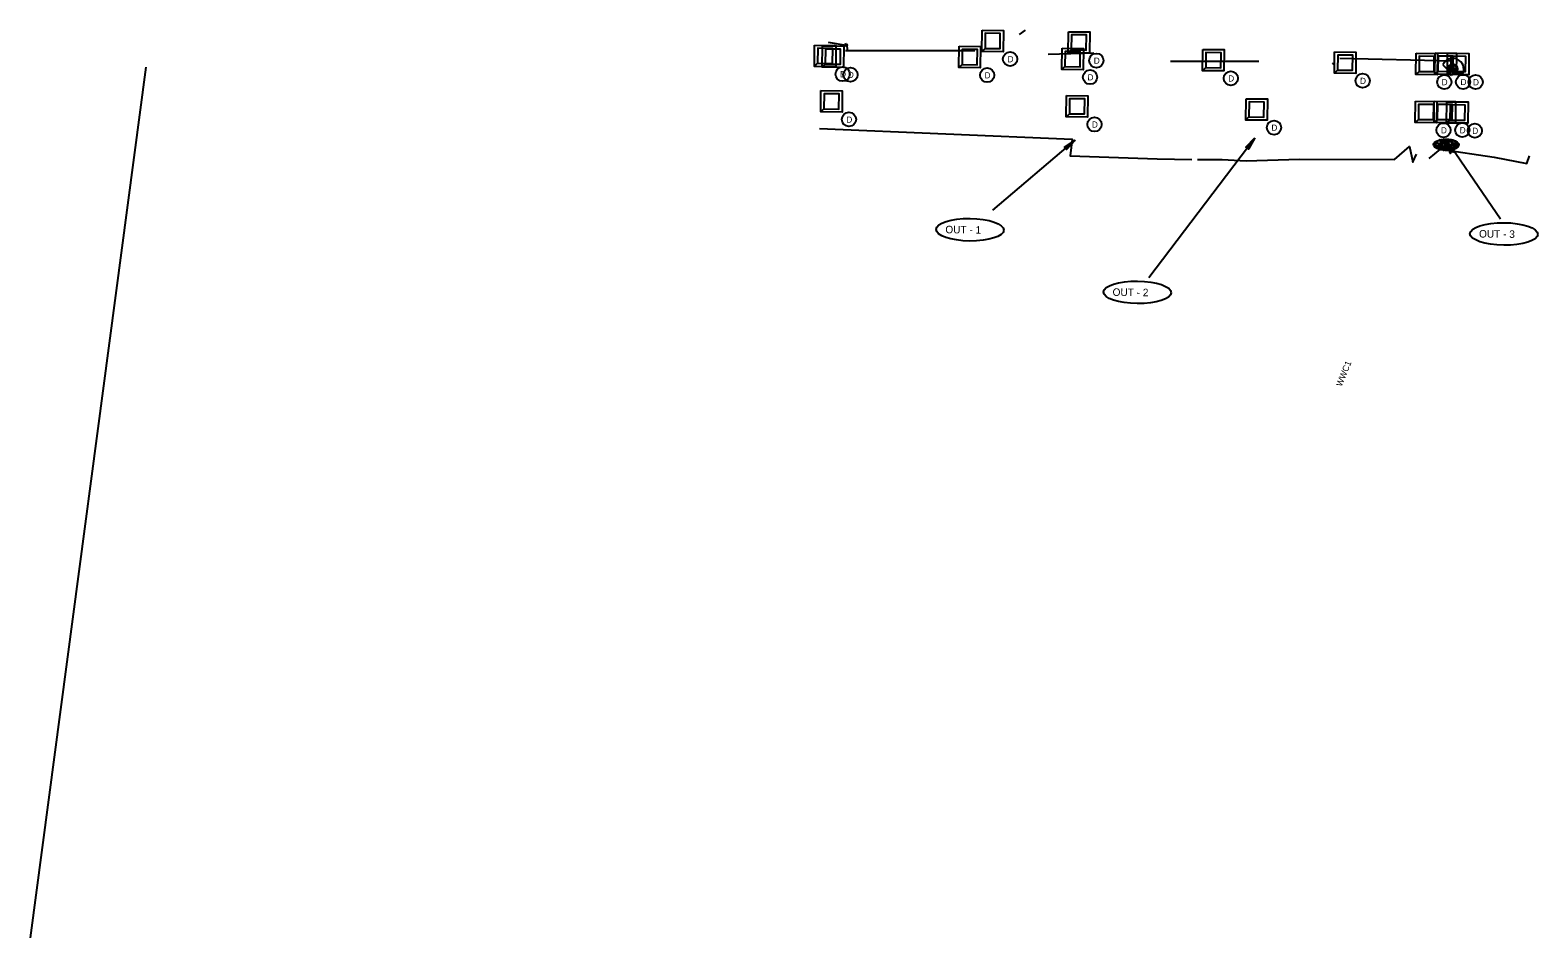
# Model space of a CAD drawing. Extents: x 1200000 to 1692190, y 507547 to 1200000.
# Drawn here: x 1680830 to 1682031, y 517488 to 518211 of the extents above; entities that cross this region are included whole.
import ezdxf

# ---------------------------------------------------------------- set-up
doc = ezdxf.new("R2010")
doc.units = 0
for name, color, linetype in [('DESIGN - EROSION CONTROL - Devices', 7, 'Continuous'), ('DESIGN - EROSION CONTROL - Devices Text and Legends', 7, 'Continuous'), ('SURVEY - MISCELLANEOUS - Office with Text', 7, 'Continuous')]:
    doc.layers.add(name, color=color, linetype=linetype)

msp = doc.modelspace()

# ---------------------------------------------------------------- linework, layer by layer
at = {"layer": 'DESIGN - EROSION CONTROL - Devices'}
for p, q in [((1681587.8, 518194.1), (1681588, 518211.1)), ((1681617.9, 518207.8), (1681622.6, 518211.1)), ((1681656.5, 518192.9), (1681656.7, 518209.9)), ((1681454.4, 518182.2), (1681454.6, 518199.2)), ((1681460.6, 518181.6), (1681460.8, 518198.6)), ((1681465.4, 518201.6), (1681481, 518199)), ((1681478.8, 518200.8), (1681479.7, 518198)), ((1681479.3, 518194.9), (1681582.3, 518194.8)), ((1681479.7, 518198), (1681480.3, 518200.2)), ((1681480.3, 518200.2), (1681480.5, 518194.7)), ((1681569.5, 518181.3), (1681569.7, 518198.3)), ((1681640.6, 518192.1), (1681677, 518193)), ((1681651.5, 518179.7), (1681651.7, 518196.7)), ((1681763.6, 518178.8), (1681763.8, 518195.8)), ((1681868.6, 518176.9), (1681868.8, 518193.9)), ((1681933.6, 518175.9), (1681933.8, 518192.9)), ((1681948.6, 518176), (1681948.8, 518193)), ((1681958.6, 518175.8), (1681958.8, 518192.8)), ((1681738, 518186.4), (1681808.4, 518186.3)), ((1681866.8, 518184.7), (1681868.8, 518183.4)), ((1681872.9, 518188.7), (1681963, 518186.8)), ((1681955.1, 518183.5), (1681959.6, 518178.9)), ((1681962.1, 518180.4), (1681960.1, 518175.9)), ((1681964, 518179.6), (1681962.1, 518180.4)), ((1681962, 518175.1), (1681960.1, 518175.9)), ((1681964, 518179.6), (1681962, 518175.1)), ((1681971, 518176.5), (1681964.6, 518176.7)), ((1681459.4, 518146), (1681459.6, 518163)), ((1681655, 518142.1), (1681655.2, 518159.1)), ((1681798, 518139.5), (1681798.2, 518156.5)), ((1681933, 518137.5), (1681933.2, 518154.5)), ((1681948, 518137.6), (1681948.2, 518154.6)), ((1681958, 518137.1), (1681958.2, 518154.1))]:
    msp.add_line(p, q, dxfattribs=at)
for points in [[(1681588, 518211.1), (1681605, 518210.9), (1681604.8, 518193.9), (1681587.8, 518194.1), (1681590.3, 518196.6), (1681602.3, 518196.5), (1681602.5, 518208.4), (1681590.5, 518208.6), (1681590.3, 518196.6), (1681587.8, 518194.1)], [(1681656.7, 518209.9), (1681673.7, 518209.7), (1681673.5, 518192.7), (1681656.5, 518192.9), (1681659, 518195.4), (1681671, 518195.3), (1681671.2, 518207.3), (1681659.2, 518207.4), (1681659, 518195.4), (1681656.5, 518192.9)], [(1681454.6, 518199.2), (1681471.6, 518199), (1681471.4, 518182), (1681454.4, 518182.2), (1681456.9, 518184.7), (1681468.9, 518184.5), (1681469.1, 518196.5), (1681457.1, 518196.7), (1681456.9, 518184.7), (1681454.4, 518182.2)], [(1681460.8, 518198.6), (1681477.8, 518198.4), (1681477.6, 518181.4), (1681460.6, 518181.6), (1681463.1, 518184.1), (1681475.1, 518183.9), (1681475.3, 518195.9), (1681463.3, 518196.1), (1681463.1, 518184.1), (1681460.6, 518181.6)], [(1681569.7, 518198.3), (1681586.7, 518198.1), (1681586.5, 518181.1), (1681569.5, 518181.3), (1681572, 518183.8), (1681584, 518183.6), (1681584.2, 518195.6), (1681572.2, 518195.8), (1681572, 518183.8), (1681569.5, 518181.3)], [(1681651.7, 518196.7), (1681668.7, 518196.5), (1681668.5, 518179.5), (1681651.5, 518179.7), (1681654, 518182.2), (1681666, 518182), (1681666.2, 518194), (1681654.2, 518194.2), (1681654, 518182.2), (1681651.5, 518179.7)], [(1681763.8, 518195.8), (1681780.8, 518195.6), (1681780.6, 518178.6), (1681763.6, 518178.8), (1681766.1, 518181.3), (1681778.1, 518181.1), (1681778.3, 518193.1), (1681766.3, 518193.3), (1681766.1, 518181.3), (1681763.6, 518178.8)], [(1681868.8, 518193.9), (1681885.8, 518193.6), (1681885.6, 518176.6), (1681868.6, 518176.9), (1681871.1, 518179.3), (1681883.1, 518179.2), (1681883.3, 518191.2), (1681871.3, 518191.3), (1681871.1, 518179.3), (1681868.6, 518176.9)], [(1681933.8, 518192.9), (1681950.8, 518192.6), (1681950.6, 518175.6), (1681933.6, 518175.9), (1681936.1, 518178.3), (1681948.1, 518178.2), (1681948.2, 518190.2), (1681936.2, 518190.3), (1681936.1, 518178.3), (1681933.6, 518175.9)], [(1681948.8, 518193), (1681965.8, 518192.8), (1681965.6, 518175.8), (1681948.6, 518176), (1681951.1, 518178.4), (1681963.1, 518178.3), (1681963.3, 518190.3), (1681951.3, 518190.4), (1681951.1, 518178.4), (1681948.6, 518176)], [(1681958.8, 518192.8), (1681975.8, 518192.6), (1681975.6, 518175.6), (1681958.6, 518175.8), (1681961.1, 518178.3), (1681973.1, 518178.1), (1681973.3, 518190.1), (1681961.3, 518190.3), (1681961.1, 518178.3), (1681958.6, 518175.8)], [(1681459.6, 518163), (1681476.6, 518162.8), (1681476.4, 518145.8), (1681459.4, 518146), (1681461.9, 518148.5), (1681473.9, 518148.3), (1681474.1, 518160.3), (1681462.1, 518160.5), (1681461.9, 518148.5), (1681459.4, 518146)], [(1681655.2, 518159.1), (1681672.2, 518158.8), (1681672, 518141.8), (1681655, 518142.1), (1681657.5, 518144.5), (1681669.5, 518144.4), (1681669.7, 518156.4), (1681657.7, 518156.5), (1681657.5, 518144.5), (1681655, 518142.1)], [(1681798.2, 518156.5), (1681815.2, 518156.3), (1681815, 518139.3), (1681798, 518139.5), (1681800.5, 518142), (1681812.5, 518141.8), (1681812.7, 518153.8), (1681800.7, 518154), (1681800.5, 518142), (1681798, 518139.5)], [(1681933.2, 518154.5), (1681950.2, 518154.2), (1681950, 518137.2), (1681933, 518137.5), (1681935.5, 518139.9), (1681947.5, 518139.8), (1681947.7, 518151.8), (1681935.7, 518151.9), (1681935.5, 518139.9), (1681933, 518137.5)], [(1681948.2, 518154.6), (1681965.2, 518154.3), (1681965, 518137.3), (1681948, 518137.6), (1681950.5, 518140), (1681962.5, 518139.9), (1681962.7, 518151.9), (1681950.7, 518152), (1681950.5, 518140), (1681948, 518137.6)], [(1681958.2, 518154.1), (1681975.2, 518153.9), (1681975, 518136.9), (1681958, 518137.1), (1681960.5, 518139.5), (1681972.5, 518139.4), (1681972.7, 518151.4), (1681960.7, 518151.5), (1681960.5, 518139.5), (1681958, 518137.1)], [(1681458.4, 518132.8), (1681659.8, 518124.2), (1681658.2, 518111), (1681727.5, 518108.6), (1681755, 518108.1)], [(1681759.6, 518108.1), (1681779.2, 518108.1), (1681798.3, 518106.9), (1681840.9, 518108.2), (1681916.5, 518108.1), (1681928.5, 518118.5), (1681931.1, 518105.8), (1681933.9, 518112.3)], [(1681944, 518108.8), (1681953.2, 518116.2), (1681995.8, 518109.9), (1682021.8, 518105), (1682023.9, 518111.1)]]:
    msp.add_lwpolyline(points, dxfattribs=at)
for points in [[(1681965.4, 518118.9), (1681967.4, 518118.9), (1681967.4, 518120.3), (1681966.2, 518120.2)], [(1681950, 518117.2), (1681951.9, 518117.2), (1681952.1, 518118.7), (1681950.8, 518118.6)], [(1681956.5, 518115.6), (1681958.4, 518115.6), (1681958.5, 518117.1), (1681957.3, 518117)]]:
    msp.add_lwpolyline(points, close=True, dxfattribs=at)
for centre in [(1681610.3, 518188.1), (1681679, 518186.9), (1681476.9, 518176.1), (1681483.1, 518175.6), (1681592, 518175.3), (1681674, 518173.7), (1681786.1, 518172.8), (1681891.1, 518170.8), (1681956.1, 518169.8), (1681971.1, 518169.9), (1681981.1, 518169.8), (1681481.9, 518140), (1681677.5, 518136), (1681820.5, 518133.5), (1681955.5, 518131.4), (1681970.5, 518131.5), (1681980.5, 518131)]:
    msp.add_circle(centre, 5.68, dxfattribs=at)
for radius, start, end in [(8.66, 336.1229, 156.1229), (3.94, 336.1229, 156.1229), (2.95, 336.1229, 156.1229), (1.39, 291.1229, 201.1229)]:
    msp.add_arc((1681963, 518180), radius, start, end, dxfattribs=at)
for major_axis, ratio, start_param, end_param in [((-3.6, 1.59), 0.85, 0, 1.318116), ((-2.7, 1.2), 0.8, 0, 1.230959), ((3.6, -1.59), 0.85, 4.965069, 6.283185), ((2.7, -1.2), 0.8, 5.052226, 6.283185)]:
    msp.add_ellipse((1681963, 518180), major_axis=major_axis, ratio=ratio, start_param=start_param, end_param=end_param, dxfattribs=at)
msp.add_ellipse((1681957.7, 518119.8), major_axis=(10.1, -0.1), ratio=0.441611, dxfattribs=at)
for points in [[(1681947.6, 518120.1), (1681948, 518118.8), (1681949.2, 518119.1), (1681949.2, 518120.2), (1681948.5, 518120.7), (1681947.8, 518120.2)], [(1681948.5, 518121.2), (1681949.2, 518120.2), (1681950.3, 518118.8), (1681951.3, 518119.1), (1681951.4, 518120.1), (1681950.1, 518121.2), (1681948.5, 518121.5)], [(1681950.1, 518122.6), (1681950.1, 518121.9), (1681950.9, 518121), (1681951.7, 518120.6), (1681953.2, 518121.3), (1681952.8, 518123.1), (1681951.7, 518123.1), (1681950.1, 518122.6)], [(1681951.9, 518119.7), (1681952.2, 518118.4), (1681953.5, 518118.7), (1681953.5, 518119.9), (1681952.7, 518120.3), (1681952, 518119.8)], [(1681952, 518123.4), (1681952.4, 518123.1), (1681952.9, 518123.7), (1681952.1, 518123.4)], [(1681953.3, 518123.5), (1681953.6, 518122.3), (1681954.9, 518122.6), (1681954.9, 518123.7), (1681954.2, 518123.8), (1681953.3, 518123.5)], [(1681953.5, 518121.1), (1681954.2, 518120), (1681955.3, 518118.6), (1681956.3, 518118.9), (1681956.4, 518120), (1681955.1, 518121.1), (1681953.5, 518121.3)], [(1681954, 518119.9), (1681953.6, 518119.6), (1681954, 518119.3), (1681954.4, 518119.7), (1681953.9, 518119.9)], [(1681954.2, 518122), (1681953.8, 518121.6), (1681954.2, 518121.4), (1681954.6, 518121.8), (1681954.1, 518122)], [(1681954.6, 518121.6), (1681955.3, 518121.1), (1681955.6, 518120.9), (1681955.4, 518121.3), (1681955.6, 518121.5), (1681955.5, 518121.8), (1681955.3, 518122), (1681955.3, 518122.5), (1681955.2, 518122.7), (1681954.9, 518122.2), (1681954.7, 518121.6)], [(1681956.8, 518124.1), (1681955.1, 518123.5), (1681955.6, 518123.3), (1681956.6, 518123.4), (1681957.3, 518124.1), (1681956.8, 518124.1)], [(1681955.4, 518122.5), (1681955.4, 518121.8), (1681956, 518122), (1681955.6, 518122.5), (1681955.4, 518122.5)], [(1681955.6, 518121.2), (1681957.2, 518120.1), (1681957.8, 518121.7), (1681956.8, 518121.4), (1681956.1, 518121.6), (1681955.5, 518121.2)], [(1681955.9, 518122.9), (1681957.6, 518121.8), (1681958.2, 518123.4), (1681957.1, 518123.2), (1681956.4, 518123.3), (1681955.8, 518123)], [(1681956.3, 518122.3), (1681956.2, 518121.7), (1681956.8, 518121.5), (1681957.1, 518121.7), (1681956.7, 518122.2), (1681956.3, 518122.2)], [(1681956.2, 518119), (1681956.5, 518117.8), (1681957.8, 518118.1), (1681957.8, 518119.3), (1681957.1, 518119.7), (1681956.4, 518119.2)], [(1681957.6, 518124.2), (1681957.6, 518123.5), (1681958.1, 518123.7), (1681957.8, 518124.1), (1681957.6, 518124.2)], [(1681957.4, 518120.3), (1681958.1, 518119.3), (1681959.2, 518117.8), (1681960.3, 518118.1), (1681960.3, 518119.1), (1681959.1, 518120.3), (1681957.4, 518120.5)], [(1681958.2, 518121.4), (1681958.2, 518120.7), (1681958.8, 518120.9), (1681958.4, 518121.4), (1681958.2, 518121.4)], [(1681958.7, 518122.8), (1681958.4, 518122.4), (1681958.8, 518122.2), (1681959.1, 518122.6), (1681958.7, 518122.8)], [(1681958.5, 518124.1), (1681958.8, 518123.1), (1681959, 518122.7), (1681959.4, 518122.6), (1681959.9, 518122.8), (1681959.2, 518123.5), (1681958.5, 518124.1)], [(1681958.8, 518120.9), (1681958.7, 518120.3), (1681959.2, 518120.1), (1681959.5, 518120.3), (1681959.1, 518120.9), (1681958.8, 518120.9)], [(1681959, 518121.8), (1681959.2, 518121), (1681960, 518120.1), (1681960.8, 518119.6), (1681962.2, 518120.4), (1681961.8, 518122.1), (1681960.8, 518122.1), (1681958.9, 518121.8)], [(1681959.9, 518122.7), (1681959.4, 518122.5), (1681959.1, 518122.1), (1681959.4, 518122), (1681960.2, 518122.2), (1681960.5, 518122.4), (1681960.1, 518122.7), (1681959.9, 518122.7)], [(1681960.3, 518123.4), (1681960.2, 518122.8), (1681960.7, 518122.5), (1681961.1, 518122.8), (1681960.6, 518123.3), (1681960.3, 518123.4)], [(1681960.9, 518119.6), (1681960.6, 518119.2), (1681961, 518119), (1681961.3, 518119.4), (1681960.9, 518119.6)], [(1681962.5, 518119.8), (1681960.9, 518119.2), (1681961.3, 518119), (1681962.4, 518119.1), (1681963, 518119.8), (1681962.5, 518119.8)], [(1681961, 518123.9), (1681961, 518123.1), (1681961.6, 518123.3), (1681961.2, 518123.8), (1681961, 518123.9)], [(1681961.5, 518123.1), (1681961.9, 518122.4), (1681962.3, 518122.4), (1681962.2, 518122.8), (1681961.5, 518123.1)], [(1681962, 518123.2), (1681962.7, 518122.2), (1681963.8, 518120.8), (1681964.8, 518121.1), (1681964.9, 518122.1), (1681963.7, 518123.2), (1681962, 518123.4)], [(1681962.7, 518121), (1681962.7, 518120.3), (1681963.2, 518120.2), (1681963.4, 518120.7), (1681963.6, 518120.9), (1681963.2, 518121.1), (1681962.6, 518121.1)], [(1681963.2, 518120.2), (1681963.6, 518119.8), (1681964.2, 518120.4), (1681963.3, 518120.2)], [(1681963.5, 518119.4), (1681963.8, 518118.2), (1681965, 518118.5), (1681965, 518119.6), (1681964.3, 518120.1), (1681963.6, 518119.6)], [(1681965.2, 518121.6), (1681964.8, 518121.2), (1681965.3, 518120.9), (1681965.6, 518121.3), (1681965.1, 518121.6)], [(1681965.1, 518120.6), (1681965.2, 518119.9), (1681965.6, 518119.7), (1681965.9, 518120.2), (1681966, 518120.5), (1681965.6, 518120.6), (1681965, 518120.6)], [(1681965.4, 518122.4), (1681965.6, 518121.5), (1681965.8, 518121.1), (1681966.2, 518121), (1681966.8, 518121.3), (1681966.1, 518121.9), (1681965.4, 518122.5)], [(1681966.9, 518121.1), (1681966.6, 518120.7), (1681967, 518120.5), (1681967.3, 518120.9), (1681966.8, 518121.1)], [(1681949.5, 518119.1), (1681948.5, 518118.3), (1681949.4, 518117.7), (1681950.2, 518118.3), (1681949.5, 518119.1)], [(1681951.8, 518117.1), (1681951.8, 518116.6), (1681952.3, 518116.3), (1681952.6, 518116.5), (1681952.2, 518117.1), (1681951.8, 518117.1)], [(1681952.2, 518118), (1681952.3, 518117.2), (1681952.8, 518117.4), (1681952.4, 518117.9), (1681952.2, 518117.9)], [(1681952.6, 518118), (1681954.3, 518116.9), (1681954.9, 518118.5), (1681953.8, 518118.2), (1681953.2, 518118.4), (1681952.5, 518118)], [(1681952.7, 518117.3), (1681953, 518116.4), (1681953.2, 518116), (1681953.6, 518116), (1681954.1, 518116.2), (1681953.5, 518116.9), (1681952.7, 518117.5)], [(1681954.2, 518119), (1681953.9, 518118.7), (1681954.3, 518118.5), (1681954.6, 518118.8), (1681954.2, 518119)], [(1681954.3, 518116.5), (1681955.9, 518115.5), (1681956.5, 518117.1), (1681955.4, 518116.8), (1681954.8, 518116.9), (1681954.2, 518116.6)], [(1681955.1, 518118.4), (1681955.3, 518117.4), (1681955.5, 518117.1), (1681955.9, 518117), (1681956.5, 518117.3), (1681955.8, 518117.9), (1681955.1, 518118.5)], [(1681957.4, 518117.9), (1681957.3, 518117.3), (1681957.9, 518117.1), (1681958.2, 518117.3), (1681957.8, 518117.8), (1681957.4, 518117.9)], [(1681958.3, 518118), (1681958.4, 518117.2), (1681958.8, 518116.9), (1681959.1, 518117.2), (1681959.3, 518117.6), (1681958.6, 518118), (1681958.3, 518118.1)], [(1681960.2, 518117.2), (1681959.2, 518116), (1681960.2, 518115.8), (1681960.9, 518116.4), (1681960.1, 518117.2)], [(1681960.4, 518118.4), (1681960.5, 518117.6), (1681961.3, 518116.7), (1681962.1, 518116.3), (1681963.6, 518117), (1681963.2, 518118.8), (1681962.2, 518118.8), (1681960.4, 518118.3)], [(1681961.2, 518116.3), (1681960.9, 518115.9), (1681961.3, 518115.7), (1681961.6, 518116.1), (1681961.2, 518116.3)], [(1681963.9, 518117), (1681964.4, 518116.6), (1681964.4, 518116.5), (1681964.5, 518116.8), (1681964.7, 518117), (1681964.5, 518117.3), (1681964.3, 518117.5), (1681964.6, 518117.8), (1681964.5, 518118), (1681964, 518117.7), (1681963.9, 518117.1)], [(1681964.9, 518118.1), (1681964.9, 518117.4), (1681965.4, 518117.5), (1681965.1, 518118), (1681964.9, 518118)], [(1681965.3, 518118.8), (1681965.3, 518118.3), (1681965.8, 518118), (1681966.1, 518118.2), (1681965.7, 518118.8), (1681965.3, 518118.8)], [(1681966.3, 518118.7), (1681966.3, 518117.9), (1681966.9, 518118.1), (1681966.5, 518118.6), (1681966.3, 518118.6)]]:
    msp.add_spline(points, degree=3, dxfattribs=at)
at = {"layer": 'DESIGN - EROSION CONTROL - Devices Text and Legends'}
for p, q in [((1681596.6, 518067.7), (1681662.1, 518123.4)), ((1681720.8, 518014.1), (1681805.2, 518125.2)), ((1682000.8, 518060.5), (1681958.5, 518122.7))]:
    msp.add_line(p, q, dxfattribs=at)
for points in [[(1681662.1, 518123.4), (1681655.2, 518115.9), (1681655.4, 518117.7), (1681653.6, 518117.9)], [(1681805.2, 518125.2), (1681800.1, 518116.4), (1681799.9, 518118.2), (1681798, 518118)], [(1681958.5, 518122.7), (1681963.1, 518113.8), (1681961.5, 518114.5), (1681960.8, 518112.9)]]:
    msp.add_lwpolyline(points, close=True, dxfattribs=at)
for points in [[(1681662.1, 518123.4), (1681655.2, 518115.9), (1681655.4, 518117.7), (1681653.6, 518117.9), (1681662.1, 518123.4)], [(1681805.2, 518125.2), (1681800.1, 518116.4), (1681799.9, 518118.2), (1681798, 518118), (1681805.2, 518125.2)], [(1681958.5, 518122.7), (1681963.1, 518113.8), (1681961.5, 518114.5), (1681960.8, 518112.9), (1681958.5, 518122.7)]]:
    msp.add_lwpolyline(points, dxfattribs=at)
for centre in [(1681578.3, 518052.1), (1682003.6, 518048.7), (1681711.7, 518002.2)]:
    msp.add_ellipse(centre, major_axis=(27, -0.3), ratio=0.333333, dxfattribs=at)
at = {"layer": 'SURVEY - MISCELLANEOUS - Office with Text'}
msp.add_line((1680921.9, 518181.7), (1680829.7, 517487.8), dxfattribs=at)

# ---------------------------------------------------------------- texts
at = {"layer": 'DESIGN - EROSION CONTROL - Devices'}
for p in [(1681608.2, 518185.6), (1681676.9, 518184.4), (1681474.8, 518173.6), (1681481, 518173.1), (1681589.9, 518172.7), (1681671.9, 518171.1), (1681784, 518170.2), (1681889, 518168.3), (1681954, 518167.3), (1681969, 518167.4), (1681979, 518167.2), (1681479.8, 518137.4), (1681675.4, 518133.5), (1681818.4, 518131), (1681953.4, 518128.9), (1681968.4, 518129), (1681978.4, 518128.5)]:
    msp.add_text('D', height=4.92, rotation=359.2455, dxfattribs=at).set_placement(p)
at = {"layer": 'DESIGN - EROSION CONTROL - Devices Text and Legends'}
for s, height, rotation, p in [('OUT - 1', 6, 359.2966, (1681558.7, 518049.3)), ('OUT - 3', 6, 359.2966, (1681983.8, 518045.9)), ('OUT - 2', 6, 359.2966, (1681691.9, 517999.4)), ('WWC1', 5, 67.9913, (1681874.4, 517926.7))]:
    msp.add_text(s, height=height, rotation=rotation, dxfattribs=at).set_placement(p)

doc.saveas('drawing.dxf')
